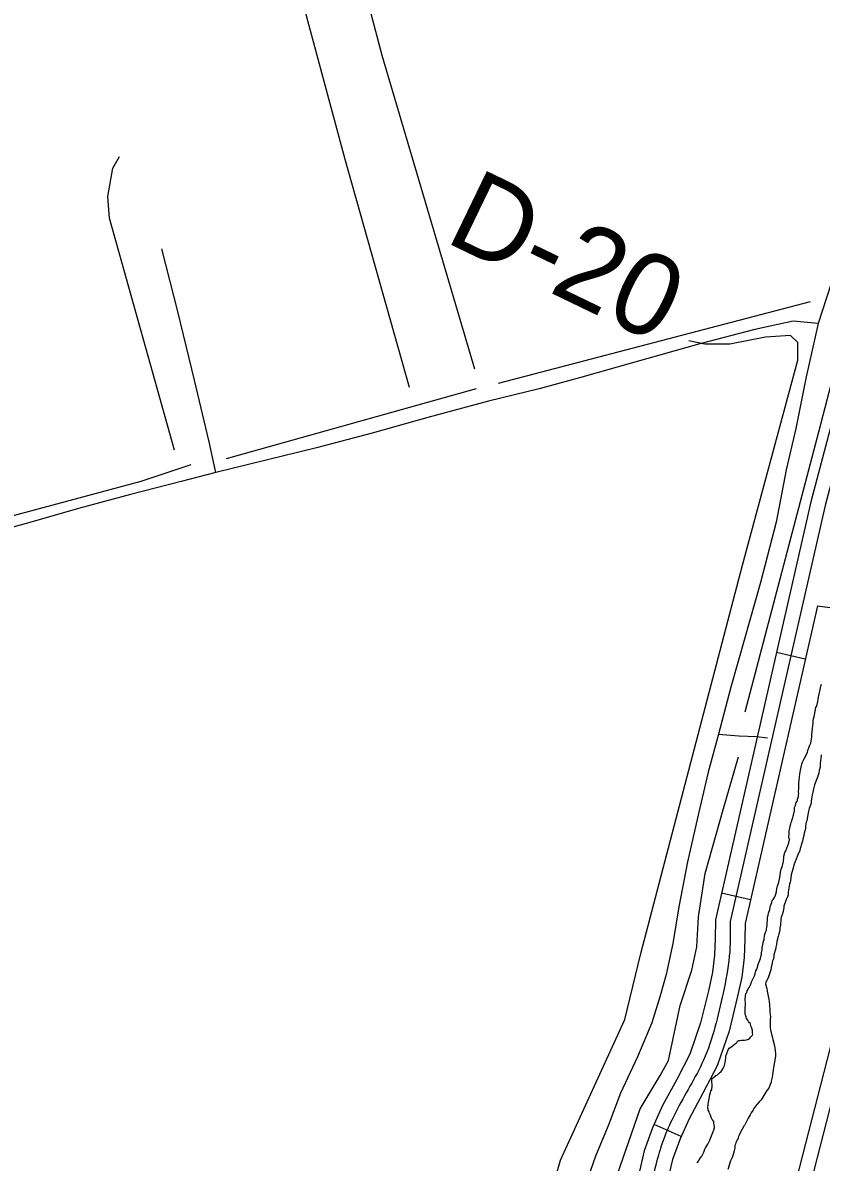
# Model space of a CAD drawing. Extents: x 3180038 to 3217926, y 922069 to 947485.
# Drawn here: x 3188795 to 3189603, y 940414 to 941568 of the extents above; entities that cross this region are included whole.
import ezdxf

# ---------------------------------------------------------------- set-up
doc = ezdxf.new("R2010")
doc.units = 0
for name, color, linetype in [('V-RIVR-RANG-IDEN', 7, 'Continuous'), ('V-ROAD-CNTR', 7, 'Continuous'), ('V-RRAP-FSHR', 7, 'Continuous'), ('V-SITE-VEGE', 7, 'Continuous'), ('V-TOPO-SHOR', 7, 'Continuous')]:
    doc.layers.add(name, color=color, linetype=linetype)

msp = doc.modelspace()

# ---------------------------------------------------------------- linework, layer by layer
at = {"layer": 'V-ROAD-CNTR'}
for p, q in [((3189587.4, 940923.3), (3189558.2, 940930)), ((3189531.9, 940679.6), (3189502.6, 940686.2)), ((3189461.7, 940439.7), (3189434.3, 940451.9))]:
    msp.add_line(p, q, dxfattribs=at)
for points in [[(3189693.9, 941463.5), (3189593, 941082.5), (3189496.5, 940659.3), (3189496.1, 940640.3), (3189495.6, 940623.5), (3189493.4, 940606.2), (3189489.6, 940588.5), (3189481.4, 940554.9), (3189470.5, 940523), (3189457.3, 940497.6), (3189442.8, 940471), (3189432.8, 940448.5), (3189424.3, 940425.1), (3189417.8, 940397.3), (3189412, 940370.9), (3189402.9, 940340), (3189392.1, 940308.2), (3189269.2, 939791.2), (3189249.2, 939728.7), (3189224.2, 939702.9)], [(3189708.4, 941459.6), (3189607.5, 941078.9), (3189511.5, 940657.4)], [(3189285, 939192.4), (3189772.5, 941091.3)], [(3189599.8, 940977.4), (3189526.4, 940655.6), (3189526.1, 940639.5), (3189525.5, 940621.2), (3189523, 940601.2), (3189518.9, 940581.8), (3189510.2, 940546.4), (3189498.1, 940511.2), (3189483.8, 940483.5), (3189469.7, 940457.8), (3189460.6, 940437.3), (3189453.1, 940416.5), (3189447, 940390.7), (3189441.1, 940363.5), (3189431.5, 940330.9), (3189421, 940299.9), (3189298.1, 939783.2), (3189275.7, 939713.2), (3189271.6, 939708.7)], [(3189599.8, 940977.4), (3189723.5, 940960.8)], [(3189270.2, 939195.2), (3189723.5, 940960.8)]]:
    msp.add_lwpolyline(points, dxfattribs=at)
msp.add_spline([(3189511.5, 940657.4), (3189510.5, 940622.4), (3189504.2, 940585.1), (3189484.3, 940517.1), (3189456.2, 940464.4), (3189438.7, 940420.8), (3189426.5, 940367.2), (3189406.6, 940304)], degree=3, dxfattribs=at)
at = {"layer": 'V-RRAP-FSHR'}
msp.add_spline([(3188909.7, 936835.6), (3188947.2, 936904.9), (3189148.2, 937330.3), (3189156.6, 937362.7), (3189315.1, 937655.2), (3189456.1, 937980.7), (3189785.8, 938633.8), (3189989.6, 939082.5), (3190086.5, 939246.3), (3190202.2, 939544.1), (3190260.4, 939640.9), (3190317.5, 939690.4), (3190371.6, 939772), (3190383.2, 939818.4), (3190378.3, 939877), (3190456.7, 940024.4), (3190526.9, 940196.4), (3190632, 940397.8), (3190706.6, 940575.7), (3190844.1, 940852.1), (3190870.7, 940905.5), (3190891.6, 940984.9), (3190926.1, 941035.4), (3191101.3, 941369.4), (3191117.2, 941389.3)], degree=3, dxfattribs=at)
at = {"layer": 'V-SITE-VEGE'}
for points in [[(3189703.5, 941645.6), (3189690.2, 941593.7), (3189680.2, 941548.9), (3189666.9, 941498.7), (3189653.8, 941452.2), (3189641.1, 941401.2), (3189628, 941354.6), (3189613.4, 941302.8), (3189600.5, 941263.1)], [(3189600.5, 941263.1), (3189575.2, 941265.4), (3189536.3, 941257), (3189480.8, 941242.5), (3189414.7, 941224.1), (3189358.8, 941208.2), (3189318.1, 941197), (3189266.9, 941184.4), (3189205.5, 941167.9), (3189148.9, 941152), (3189092.5, 941137.2), (3188990.8, 941112.2), (3188983.9, 941143.4), (3188969, 941205.8), (3188952.3, 941275.2), (3188936.2, 941338.7)], [(3189600.5, 941263.1), (3189588.4, 941209.1), (3189577.9, 941156.9), (3189568, 941114.9), (3189557.8, 941061.9), (3189542.2, 941000.8), (3189526.1, 940944.9), (3189512, 940894.8), (3189499.6, 940847.4), (3189520, 940845.6), (3189538.1, 940844.8), (3189549.3, 940843.4)], [(3188990.8, 941112.2), (3188955.7, 941103.2), (3188904.3, 941089.9), (3188851.7, 941075.9), (3188802.4, 941061.6), (3188754.2, 941048.6), (3188704.8, 941036)], [(3189499.6, 940847.4), (3189489.2, 940808.9), (3189480.8, 940772.8), (3189468, 940717.9), (3189459.4, 940672.3), (3189453.4, 940635.3), (3189446.7, 940603.9), (3189440.4, 940582.3), (3189432.1, 940555), (3189417.4, 940520.5), (3189400.5, 940483.8), (3189387.7, 940450.4), (3189375.2, 940419.7), (3189362.9, 940385.2), (3189351, 940346.8), (3189340.2, 940306.8), (3189327.4, 940258.2)]]:
    msp.add_lwpolyline(points, dxfattribs=at)
at = {"layer": 'V-TOPO-SHOR'}
for p, q in [((3189276.7, 941202.6), (3189592.5, 941285.4)), ((3189001.4, 941126.6), (3189254.7, 941197.5))]:
    msp.add_line(p, q, dxfattribs=at)
for points in [[(3189526.6, 940869.9), (3189601, 941153.6), (3189663.5, 941393.5), (3189808.7, 941955.9), (3189871.2, 942189), (3189957.3, 942501.4), (3190011.4, 942726.1)], [(3189253, 941216.9), (3189159.2, 941534.5), (3189022.1, 942054.2), (3188939.1, 942369.9), (3188937.3, 942402.4), (3188940.9, 942420.5)], [(3188857.9, 942406), (3189004, 941866.5), (3189121.3, 941429.8), (3189186.3, 941198.8)], [(3188949, 941135), (3188883.1, 941369.8), (3188881.5, 941391.8), (3188886.5, 941420.5), (3188893.3, 941432.3)], [(3188688.2, 939820.2), (3188922.8, 939822), (3189123.1, 939820.2), (3189164.6, 939823.8), (3189177.3, 939838.3), (3189271.1, 940177.5), (3189339.7, 940415.7), (3189404.6, 940558.2), (3189420.9, 940625), (3189523.7, 941018.4), (3189579.7, 941225.9), (3189579.7, 941243.9), (3189572.4, 941251.2), (3189547.2, 941249.4), (3189511.1, 941242.1), (3189485.8, 941242.1), (3189469.6, 941245.7)], [(3186800.6, 940535.9), (3187253.3, 940654.1), (3188361.3, 940954.7), (3188915.2, 941103.4), (3188965.9, 941120.3)], [(3189565.7, 940721.1), (3189565.8, 940723.7), (3189566.7, 940727.4), (3189567.8, 940729.1), (3189568.7, 940731.7), (3189570.7, 940737.1), (3189570.7, 940737.7), (3189570.9, 940738.2), (3189571.2, 940739.3), (3189571.4, 940739.9), (3189571.5, 940740.4), (3189571.7, 940741.4), (3189571.1, 940741.5), (3189570.9, 940742), (3189570.7, 940743.2), (3189570.8, 940744.4), (3189571, 940745.7), (3189571.1, 940746.8), (3189571.1, 940748.1), (3189571.2, 940749.2), (3189571.4, 940750.6), (3189571.7, 940752), (3189572, 940753.6), (3189572.4, 940755.4), (3189572.8, 940756.5), (3189573.1, 940757.7), (3189573.9, 940759.2), (3189574.1, 940760.8), (3189574.5, 940761.8), (3189574.7, 940763), (3189575.1, 940764.1), (3189575.3, 940765.1), (3189575.8, 940766.8), (3189576.2, 940768.1), (3189576.4, 940769.3), (3189576.5, 940770.7), (3189576.6, 940773), (3189577.4, 940775), (3189577.7, 940776.7), (3189578.3, 940778.2), (3189578.9, 940779), (3189579.5, 940779.9), (3189579.5, 940781.3), (3189580.1, 940783), (3189580.4, 940784.1), (3189580.4, 940785.9), (3189580.7, 940787.3), (3189580.4, 940788.7), (3189580.7, 940792.1), (3189580.7, 940793.6), (3189580.7, 940795.3), (3189581, 940797.6), (3189581.1, 940800.4), (3189582, 940807), (3189582.3, 940808.7), (3189582.6, 940810.7), (3189583.2, 940813.8), (3189584, 940817), (3189584.6, 940819), (3189585.2, 940820.4), (3189586.1, 940822.4), (3189589.6, 940828.6), (3189590.1, 940830.9), (3189590.7, 940832.3), (3189591.6, 940835.5), (3189593.1, 940838.3), (3189594, 940844.6), (3189594, 940846), (3189594, 940847.7), (3189594.3, 940849.2), (3189594.6, 940852.9), (3189595.2, 940858.3), (3189595.5, 940861.2), (3189595.8, 940862.9), (3189596.4, 940865.1), (3189596.7, 940866.9), (3189598.2, 940874.3), (3189598.8, 940875.4), (3189599.4, 940877.4), (3189600, 940880.3), (3189600.3, 940882.3), (3189600.9, 940884.8), (3189601.4, 940887.7), (3189602.3, 940892.5), (3189603.2, 940895.9), (3189603.8, 940897.9)], [(3189239.5, 939810.9), (3189391.5, 940385.1), (3189420.2, 940467.9), (3189440.5, 940501.7), (3189449, 940516.9), (3189460.8, 940572.6), (3189472.6, 940608.1), (3189477.7, 940631.7), (3189479.4, 940662.1), (3189486.1, 940706), (3189504.7, 940771.9), (3189519.9, 940824.3)], [(3189603.5, 940826.2), (3189603.2, 940822.8), (3189602.6, 940817.7), (3189602.3, 940815.4), (3189602.3, 940814), (3189601.4, 940810.5), (3189601.1, 940807.7), (3189599.7, 940803.7), (3189596.7, 940796), (3189596.4, 940794.6), (3189596.1, 940793.4), (3189595.8, 940792), (3189595, 940788.6), (3189594.4, 940785.7), (3189593.8, 940781.8), (3189593.5, 940779.5), (3189593.2, 940777.5), (3189592.6, 940775.5), (3189591.4, 940772.1), (3189590.8, 940769.2), (3189589.6, 940763.8), (3189589, 940759.5), (3189588.4, 940758.1), (3189588.1, 940756.4), (3189587.6, 940753.8), (3189587.5, 940752.1), (3189586.9, 940749), (3189586.4, 940747), (3189585.8, 940744.7), (3189585.2, 940742.4), (3189584.6, 940739), (3189583.1, 940734.7), (3189582.8, 940733.6), (3189582.2, 940731.3), (3189581.9, 940729.6), (3189579.6, 940724.4), (3189577.9, 940719.6)], [(3189513.1, 940531), (3189515.4, 940533), (3189516.3, 940533.5), (3189518, 940535), (3189518.9, 940536.4), (3189520, 940536.9), (3189521.2, 940536.9), (3189522.9, 940537.2), (3189524.6, 940537.2), (3189525.8, 940537.2), (3189527.8, 940537.7), (3189529.8, 940538.3), (3189531.2, 940539.4), (3189531.8, 940540.3), (3189533.8, 940542.3), (3189534.4, 940543.1), (3189534.1, 940544.3), (3189533.8, 940545.7), (3189533.8, 940547.1), (3189533.3, 940549.4), (3189532.4, 940551.4), (3189531.9, 940554.3), (3189530.8, 940554.9), (3189529.9, 940556.3), (3189529.1, 940557.7), (3189527.9, 940559.2), (3189527.4, 940560.9), (3189527.1, 940562), (3189526.5, 940563.2), (3189526.5, 940565.2), (3189526.6, 940566.3), (3189526.6, 940567.7), (3189526.6, 940568.9), (3189526.6, 940570.6), (3189526.9, 940572.3), (3189526.9, 940574.3), (3189526.9, 940575.5), (3189526.6, 940577.5), (3189526.7, 940579.5), (3189527.3, 940584.6), (3189528.1, 940585.7), (3189528.7, 940587.2), (3189529.3, 940588.3), (3189529.6, 940589.4), (3189530.7, 940590.8), (3189531.6, 940592.8), (3189532.2, 940594), (3189532.5, 940595.1), (3189533.1, 940596.5), (3189536, 940602.5), (3189536.6, 940604.5), (3189537.4, 940607.4), (3189538.3, 940609.4), (3189539.5, 940612.2), (3189539.5, 940613.3), (3189542.1, 940620.2), (3189542.7, 940623), (3189543, 940624.2), (3189543, 940625.9), (3189543.6, 940628.7), (3189543.9, 940630.7), (3189545.1, 940637.6), (3189545.7, 940639.3), (3189545.7, 940640.4), (3189546, 940642.2), (3189546.6, 940644.7), (3189547.5, 940647.3), (3189548, 940648.7), (3189548.1, 940650.1), (3189548.4, 940651.6), (3189548.7, 940654.4), (3189548.7, 940656.1), (3189549, 940658.1), (3189549.3, 940661.8), (3189549.9, 940663.8), (3189550.2, 940665.8), (3189551.4, 940669.8), (3189551.9, 940672.1), (3189552.2, 940673.5), (3189553.4, 940676.9), (3189554, 940678.7), (3189554.9, 940679.8), (3189555.4, 940680.9), (3189556.6, 940682.6), (3189557.2, 940684.1), (3189557.8, 940686.1), (3189558.1, 940687.8), (3189558.7, 940690.9), (3189559, 940692.3), (3189560.7, 940697.2), (3189561, 940698.9), (3189561.6, 940702), (3189561.9, 940704.6), (3189562.2, 940707.4), (3189563.1, 940710.6), (3189564, 940712.9), (3189564.6, 940716), (3189565.1, 940717.1), (3189565.2, 940718.3), (3189565.5, 940719.7), (3189565.7, 940721.1)], [(3189577.9, 940719.6), (3189577.3, 940718.2), (3189575.8, 940714.5), (3189575.5, 940713), (3189574.9, 940710.5), (3189573.2, 940704.8), (3189572.6, 940701.6), (3189572.3, 940698.8), (3189572, 940697.4), (3189571.4, 940695.4), (3189570.8, 940691.4), (3189570.5, 940689.7), (3189570.2, 940686.8), (3189569.9, 940684.5), (3189569.3, 940682.5), (3189568.1, 940679.7), (3189565.8, 940673.1), (3189565.8, 940671.7), (3189564.9, 940667.7), (3189564, 940664.3), (3189563.1, 940662), (3189562.5, 940659.4), (3189562.2, 940654), (3189561.6, 940651.2), (3189561.6, 940649.5), (3189561.3, 940646.9), (3189560.7, 940644.9), (3189560.1, 940642.3), (3189558.7, 940637.2), (3189558.3, 940634.3), (3189557.5, 940631.5), (3189557.2, 940629.2), (3189555.7, 940623.8), (3189555.4, 940622.4), (3189555.1, 940619.8), (3189554.2, 940617.8), (3189553.9, 940615.8), (3189553.3, 940612.7), (3189553, 940611), (3189552.4, 940608.7), (3189551, 940604.4), (3189550.4, 940602.4), (3189549.8, 940600.4), (3189548.9, 940598.4), (3189547.5, 940596.1), (3189547.2, 940594.1), (3189548.3, 940589.8), (3189548.8, 940587), (3189549.9, 940581.8), (3189550.5, 940579), (3189550.8, 940576.1), (3189551.3, 940573.3), (3189551.5, 940567.5), (3189551.5, 940565.5), (3189551.8, 940563.3), (3189552.1, 940560.7), (3189552, 940559), (3189552, 940555.3), (3189552, 940549.8), (3189552.3, 940547.8), (3189552.8, 940544.7), (3189553.1, 940543.5), (3189553.9, 940541.2), (3189554.7, 940538.1), (3189556.1, 940531.5), (3189556.7, 940529.2), (3189556.9, 940526.7), (3189557.2, 940523.5), (3189557.2, 940521.5), (3189556.6, 940517.2), (3189555.1, 940509.8), (3189554.8, 940507.2), (3189554.5, 940504.1), (3189554.2, 940502.4), (3189553.9, 940499.8), (3189553, 940495.8), (3189552.7, 940494.7), (3189551.8, 940492.4), (3189550.4, 940488.7), (3189548.3, 940486.4), (3189546.3, 940483), (3189543.4, 940477.9), (3189542.3, 940476.5), (3189540.8, 940474.8), (3189538.5, 940472.2), (3189537.4, 940470.8), (3189535.9, 940469.1), (3189534.2, 940466), (3189532.5, 940463.7), (3189531.6, 940461.7), (3189529.6, 940458.3), (3189526.4, 940452.3), (3189525.8, 940450.9), (3189525.2, 940450.1), (3189523.5, 940447.2), (3189521.4, 940443.5), (3189520.6, 940441.2), (3189519.7, 940439.8), (3189519.4, 940438.4), (3189519.1, 940436.7), (3189518.8, 940437)], [(3189477.9, 940413), (3189479.4, 940414.7), (3189480, 940416.1), (3189482, 940419), (3189482.6, 940419.8), (3189484, 940422.4), (3189484.6, 940423.8), (3189485.8, 940426.9), (3189486.4, 940428.4), (3189486.9, 940429.2), (3189488.7, 940432.1), (3189490.7, 940436), (3189491, 940437.2), (3189491.9, 940438.9), (3189493.3, 940442), (3189493.9, 940443.7), (3189494.8, 940446.6), (3189495.4, 940448.6), (3189495.4, 940449.7), (3189495.1, 940451.7), (3189494.8, 940453.1), (3189494.8, 940455.1), (3189493.1, 940456.9), (3189492, 940458.9), (3189491.5, 940461.5), (3189490.6, 940463.5), (3189490.1, 940464.9), (3189489.2, 940466.3), (3189489.2, 940467.5), (3189488.7, 940468.6), (3189488.7, 940469.8), (3189489, 940471.2), (3189489, 940472.6), (3189489.3, 940474.6), (3189490.2, 940478), (3189490.5, 940480), (3189490.8, 940482.3), (3189491.4, 940484), (3189491.9, 940486.3), (3189492.2, 940486.3), (3189492.8, 940487.4), (3189493.1, 940491.2), (3189493.1, 940492.9), (3189492.9, 940494.9), (3189492.9, 940496.9), (3189493.2, 940498.6), (3189494.9, 940499.7), (3189496.3, 940500.6), (3189496.9, 940501.4), (3189498.4, 940502.3), (3189500.7, 940504.2), (3189502.1, 940505.7), (3189504.7, 940509.3), (3189505.3, 940510.5), (3189505.6, 940511.9), (3189505.9, 940513.3), (3189506.2, 940514.8), (3189506.7, 940517), (3189507.1, 940519), (3189506.8, 940521.3), (3189507.4, 940522.2), (3189509.7, 940528.2), (3189510.3, 940529.3), (3189513.1, 940531)], [(3189518.8, 940437), (3189518.2, 940435.8), (3189517.1, 940433.5), (3189516.8, 940432.1), (3189516.2, 940430.7), (3189516.2, 940428.4), (3189515.3, 940425.3), (3189514.4, 940421.6), (3189513.8, 940419), (3189511.8, 940415), (3189508.9, 940406.5)]]:
    msp.add_lwpolyline(points, dxfattribs=at)

# ---------------------------------------------------------------- texts
at = {"layer": 'V-RIVR-RANG-IDEN'}
msp.add_text('D-20', height=83, rotation=334.2307, dxfattribs=at).set_placement((3189220.8, 941346.8))

doc.saveas('drawing.dxf')
